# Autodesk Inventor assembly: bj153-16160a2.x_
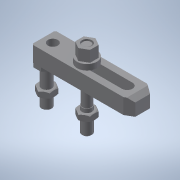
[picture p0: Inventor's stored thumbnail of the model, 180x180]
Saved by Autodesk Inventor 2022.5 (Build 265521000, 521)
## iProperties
Part Number: bj153-16160a2.x_
Material: 一般
Document SubType Name: Assembly
Designer: ImaoCorp
Sending System: SOLIDWORKS 2017-2017317
MC: AMD64
MC_MODEL: Intel64 Family 6 Model 60 Stepping 3, GenuineIntel
OS: Windows_NT
FRU: Parasolid Version 29.0, build 201,  4-17-2017
FORMAT: text
GUISE: transmit
KEY: bj153-16160a2
FILE: bj153-16160a2.x_t
DATE: Fri Mar 15 10:22:56 2019
Author: ImaoCorp
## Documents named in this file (7)
- X:\14_SW2022-Inv2022\00_全2023-1023新製品(TCC)まで\b\bj153-16160a2\BJ153-16160A2.iam
- X:\14_SW2022-Inv2022\00_全2023-1023新製品(TCC)まで\b\bj153-16160a2\bj153-16160a2_01.ipt
- X:\14_SW2022-Inv2022\00_全2023-1023新製品(TCC)まで\b\bj153-16160a2\bj153-16160a2_02.ipt
- X:\14_SW2022-Inv2022\00_全2023-1023新製品(TCC)まで\b\bj153-16160a2\bj153-16160a2_03.ipt
- X:\14_SW2022-Inv2022\00_全2023-1023新製品(TCC)まで\b\bj153-16160a2\bj153-16160a2_04.ipt
- X:\14_SW2022-Inv2022\00_全2023-1023新製品(TCC)まで\b\bj153-16160a2\bj153-16160a2_05.ipt
- X:\14_SW2022-Inv2022\00_全2023-1023新製品(TCC)まで\b\bj153-16160a2\bj153-16160a2_06.ipt
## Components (6 placed, 6 different names)
1. bj153-16160a2_01
2. bj153-16160a2_02
3. bj153-16160a2_03
4. bj153-16160a2_04
5. bj153-16160a2_05
6. bj153-16160a2_06
